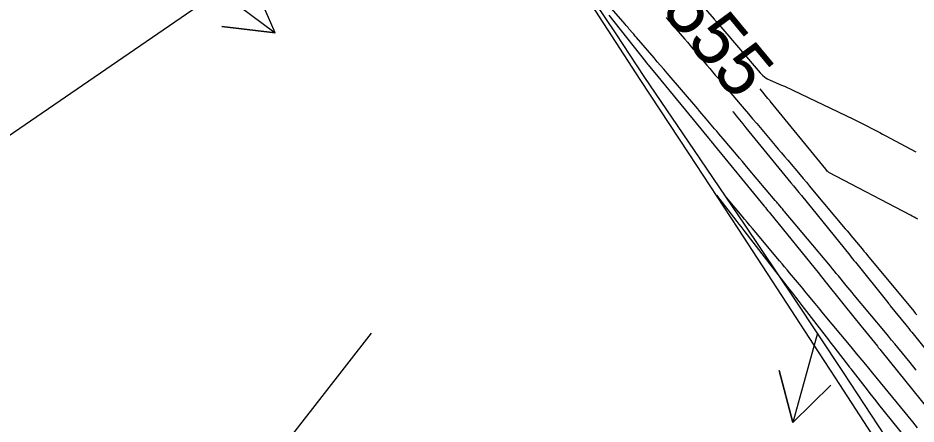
# Model space of a CAD drawing. Extents: x 954385 to 988206, y 1868364 to 1924553.
# Drawn here: x 957517.5 to 957618.2, y 1920108.8 to 1920154.3 of the extents above; entities that cross this region are included whole.
import ezdxf

# ---------------------------------------------------------------- set-up
doc = ezdxf.new("R2010")
doc.units = 0
for name, color, linetype in [('16', 7, 'Continuous'), ('24', 7, 'Continuous'), ('26', 7, 'Continuous'), ('6', 7, 'Continuous'), ('7', 7, 'Continuous')]:
    doc.layers.add(name, color=color, linetype=linetype)

msp = doc.modelspace()

# ---------------------------------------------------------------- linework, layer by layer
at = {"layer": '16'}
for points in [[(957620.08, 1920097.17), (957614.6, 1920105.54), (957609.15, 1920113.92), (957607.25, 1920116.85), (957603.71, 1920122.32), (957598.24, 1920130.69), (957592.75, 1920139.05), (957587.26, 1920147.4), (957581.81, 1920155.79), (957576.32, 1920164.15), (957570.81, 1920172.5), (957567.7, 1920177.52), (957565.55, 1920181.01), (957560.29, 1920189.53), (957544.48, 1920190.91), (957539.51, 1920199.62), (957534.53, 1920208.32), (957529.51, 1920217), (957531.24, 1920230.24), (957525.3, 1920238.3), (957519.39, 1920246.37)], [(957583.73, 1920154.59), (957587.85, 1920149.39), (957587.93, 1920149.29), (957588, 1920149.2), (957588.08, 1920149.1), (957588.16, 1920149.01), (957588.67, 1920148.39), (957588.7, 1920148.36), (957588.7, 1920148.35), (957594.93, 1920140.81), (957595, 1920140.72), (957595.08, 1920140.62), (957595.16, 1920140.53), (957595.23, 1920140.43), (957601.15, 1920133.2), (957601.29, 1920133.02), (957601.43, 1920132.85), (957601.57, 1920132.67), (957601.72, 1920132.5), (957607.34, 1920125.55), (957607.54, 1920125.3), (957607.75, 1920125.04), (957607.95, 1920124.79), (957608.15, 1920124.54), (957611.51, 1920120.36), (957611.67, 1920120.15), (957611.84, 1920119.95), (957612, 1920119.75), (957612.16, 1920119.55), (957613.84, 1920117.47), (957613.94, 1920117.35), (957614.04, 1920117.23), (957614.14, 1920117.11), (957614.24, 1920116.99), (957619.68, 1920110.22)], [(957618.36, 1920131.72), (957618.16, 1920131.83), (957617.95, 1920131.95), (957617.74, 1920132.06), (957617.54, 1920132.17), (957608.4, 1920136.96), (957608.36, 1920136.99), (957608.33, 1920137.02), (957608.29, 1920137.05), (957608.26, 1920137.08), (957608.06, 1920137.33), (957608.05, 1920137.34), (957601.84, 1920144.94), (957601.78, 1920145.02), (957601.71, 1920145.11), (957601.64, 1920145.19), (957601.57, 1920145.27), (957600.69, 1920146.34)], [(957597.62, 1920143.8), (957597.67, 1920143.74), (957598.03, 1920143.3), (957598.39, 1920142.86), (957598.75, 1920142.42), (957599.11, 1920141.98), (957604.16, 1920135.81), (957604.45, 1920135.45), (957604.75, 1920135.09), (957605.04, 1920134.73), (957605.33, 1920134.36), (957610.75, 1920127.67), (957610.9, 1920127.48), (957611.06, 1920127.29), (957611.21, 1920127.09), (957611.37, 1920126.9), (957615.01, 1920122.37), (957615.08, 1920122.28), (957615.15, 1920122.19), (957615.22, 1920122.11), (957615.29, 1920122.02), (957617.01, 1920119.89), (957617.18, 1920119.68), (957617.35, 1920119.47), (957617.52, 1920119.26), (957617.69, 1920119.05), (957623.42, 1920111.93)], [(957595.8, 1920134.4), (957598.09, 1920131.47), (957598.32, 1920131.18), (957598.54, 1920130.89), (957598.77, 1920130.6), (957598.99, 1920130.31), (957603.97, 1920123.88), (957604.32, 1920123.42), (957604.68, 1920122.97), (957605.03, 1920122.51), (957605.38, 1920122.06), (957608.36, 1920118.18), (957608.51, 1920117.99), (957608.66, 1920117.8), (957608.8, 1920117.61), (957608.95, 1920117.42), (957610.73, 1920115.13), (957610.76, 1920115.08), (957610.8, 1920115.04), (957610.83, 1920114.99), (957610.87, 1920114.95), (957612.69, 1920112.58), (957613.01, 1920112.17), (957613.33, 1920111.76), (957613.65, 1920111.36), (957613.97, 1920110.95), (957616.95, 1920107.26)]]:
    msp.add_lwpolyline(points, dxfattribs=at)
at = {"layer": '24'}
msp.add_lwpolyline([(957621.03, 1920097.81), (957615.52, 1920106.16), (957610.04, 1920114.52), (957604.51, 1920122.86), (957598.94, 1920131.16), (957593.33, 1920139.44), (957587.72, 1920147.72), (957584.55, 1920152.49), (957582.19, 1920156.05), (957576.65, 1920164.37), (957571.06, 1920172.67), (957565.83, 1920181.2), (957550.79, 1920183.1), (957545.87, 1920191.85), (957540.97, 1920200.61), (957535.89, 1920209.24), (957530.67, 1920217.78), (957527.96, 1920219.85), (957523.6, 1920225.08), (957518.05, 1920233.39), (957517.7, 1920245.23)], dxfattribs=at)
at = {"layer": '26'}
for points in [[(957457.13, 1920218.93), (957546.34, 1920152.63), (957540.38, 1920153.32), (957546.34, 1920152.63), (957543.96, 1920158.14)], [(957557.13, 1920168.93), (957420.08, 1920074.89), (957422.67, 1920080.3), (957420.08, 1920074.89), (957426.06, 1920075.36)], [(957557.13, 1920118.93), (957540.28, 1920097.31), (957541.11, 1920103.25), (957540.28, 1920097.31), (957545.84, 1920099.56)], [(957607.13, 1920118.93), (957604.35, 1920108.93), (957602.85, 1920114.74), (957604.35, 1920108.93), (957608.63, 1920113.13)]]:
    msp.add_lwpolyline(points, dxfattribs=at)
at = {"layer": '6'}
msp.add_lwpolyline([(957592.58, 1920157.63), (957595.55, 1920154.16), (957595.62, 1920154.09), (957595.68, 1920154.01), (957595.74, 1920153.94), (957595.8, 1920153.87), (957596.05, 1920153.58), (957596.11, 1920153.51), (957596.17, 1920153.44), (957596.24, 1920153.36), (957596.3, 1920153.29), (957600.71, 1920148.12), (957600.95, 1920147.87), (957601.21, 1920147.65), (957601.5, 1920147.46), (957601.81, 1920147.31), (957603.1, 1920146.76), (957603.42, 1920146.62), (957603.74, 1920146.48), (957604.06, 1920146.33), (957604.37, 1920146.18), (957611.16, 1920142.92), (957611.46, 1920142.78), (957611.76, 1920142.63), (957612.05, 1920142.48), (957612.35, 1920142.33), (957613.53, 1920141.73), (957613.83, 1920141.58), (957614.12, 1920141.43), (957614.41, 1920141.27), (957614.71, 1920141.12), (957618.14, 1920139.28)], dxfattribs=at)
at = {"layer": '7'}
for points in [[(957618.2, 1920114.81), (957617.51, 1920115.65), (957616.12, 1920117.33), (957615.78, 1920117.75), (957615.43, 1920118.17), (957615.09, 1920118.59), (957614.74, 1920119.01), (957611.25, 1920123.22), (957611.02, 1920123.49), (957610.8, 1920123.76), (957610.58, 1920124.03), (957610.36, 1920124.29), (957609.47, 1920125.37), (957609.24, 1920125.64), (957609.02, 1920125.91), (957608.8, 1920126.17), (957608.57, 1920126.44), (957603.45, 1920132.57), (957603.36, 1920132.67), (957603.27, 1920132.78), (957603.19, 1920132.88), (957603.1, 1920132.99), (957602.75, 1920133.41), (957602.66, 1920133.51), (957602.57, 1920133.62), (957602.48, 1920133.72), (957602.4, 1920133.83), (957599.36, 1920137.41), (957599.04, 1920137.8), (957598.71, 1920138.19), (957598.38, 1920138.58), (957598.05, 1920138.97), (957596.55, 1920140.74), (957596.31, 1920141.02), (957596.08, 1920141.3), (957595.84, 1920141.58), (957595.6, 1920141.85), (957594.66, 1920142.97), (957594.42, 1920143.24), (957594.18, 1920143.52), (957593.95, 1920143.8), (957593.71, 1920144.08), (957590.27, 1920148.1), (957589.91, 1920148.53), (957589.55, 1920148.95), (957589.18, 1920149.38), (957588.82, 1920149.8), (957586.85, 1920152.1), (957586.74, 1920152.22), (957586.64, 1920152.35), (957586.53, 1920152.47), (957586.42, 1920152.59), (957586, 1920153.08), (957585.9, 1920153.21), (957585.79, 1920153.33), (957585.69, 1920153.45), (957585.58, 1920153.58), (957583, 1920156.59)], [(957590.16, 1920154.34), (957590.28, 1920154.2), (957592.23, 1920151.93), (957592.55, 1920151.56), (957592.86, 1920151.19), (957593.17, 1920150.83), (957593.49, 1920150.46), (957594.74, 1920148.99), (957595.06, 1920148.62), (957595.37, 1920148.25), (957595.68, 1920147.88), (957596, 1920147.52), (957598.46, 1920144.63), (957598.93, 1920144.08), (957599.39, 1920143.54), (957599.85, 1920142.99), (957600.32, 1920142.44), (957602.39, 1920139.99), (957602.74, 1920139.57), (957603.09, 1920139.16), (957603.44, 1920138.75), (957603.79, 1920138.33), (957605.19, 1920136.68), (957605.53, 1920136.27), (957605.88, 1920135.86), (957606.23, 1920135.44), (957606.58, 1920135.03), (957610.24, 1920130.65), (957610.45, 1920130.4), (957610.66, 1920130.15), (957610.87, 1920129.9), (957611.08, 1920129.65), (957611.91, 1920128.65), (957612.12, 1920128.4), (957612.33, 1920128.15), (957612.54, 1920127.9), (957612.75, 1920127.65), (957617.93, 1920121.4), (957618.09, 1920121.2), (957618.26, 1920121.01)], [(957618.35, 1920108.34), (957617.8, 1920109.01), (957613.33, 1920114.45), (957612.73, 1920115.19), (957612.12, 1920115.93), (957611.51, 1920116.67), (957610.9, 1920117.4), (957607.63, 1920121.35), (957607.43, 1920121.58), (957607.24, 1920121.81), (957607.05, 1920122.04), (957606.86, 1920122.28), (957606.09, 1920123.2), (957605.9, 1920123.43), (957605.71, 1920123.66), (957605.51, 1920123.9), (957605.32, 1920124.13), (957604.01, 1920125.7), (957603.72, 1920126.04), (957603.44, 1920126.38), (957603.16, 1920126.71), (957602.87, 1920127.05), (957599.84, 1920130.68), (957599.55, 1920131.03), (957599.26, 1920131.37), (957598.96, 1920131.72), (957598.67, 1920132.07), (957596.92, 1920134.15)]]:
    msp.add_lwpolyline(points, dxfattribs=at)

# ---------------------------------------------------------------- texts
at = {"layer": '16'}
msp.add_text('555', height=6, rotation=309.633, dxfattribs=at).set_placement((957589.49, 1920155.15))

doc.saveas('drawing.dxf')
